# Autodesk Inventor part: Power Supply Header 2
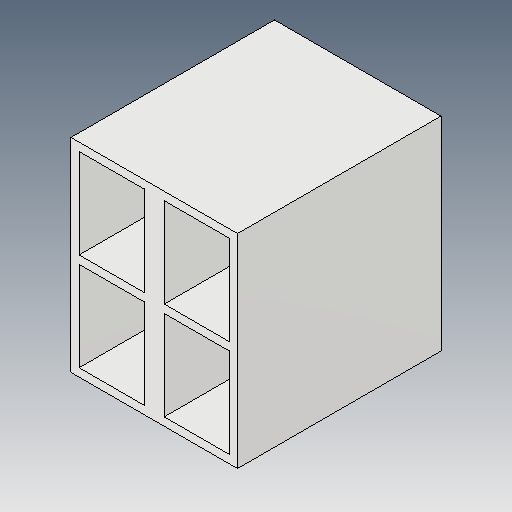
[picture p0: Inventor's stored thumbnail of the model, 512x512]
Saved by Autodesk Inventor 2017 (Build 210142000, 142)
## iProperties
Created: 2005-12
Part Number: Power Supply Header 2
Material: Generic
Document SubType Name: Modeling
Designer: DanielSeverino
Density: 1 g/cm^3
Appearance: Default
Author: DanielSeverino
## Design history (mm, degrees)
feature "Solid1"
body "Solid2"
